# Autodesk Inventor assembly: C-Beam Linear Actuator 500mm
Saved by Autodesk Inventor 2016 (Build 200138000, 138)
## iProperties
Created: 2015-11
Part Number: C-Beam Linear Actuator 500mm
Document SubType Name: Assembly
Designer: John
Author: John
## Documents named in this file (19)
- D:\3D Printer Designs\John Ledden Designs\DLP Printer\V0-4\C-Beam Linear Actuator 500mm.iam
- D:\3D Printer Designs\John Ledden Designs\DLP Printer\V0-4\Low Profile Screw M5_M5 x 20.ipt
- D:\3D Printer Designs\John Ledden Designs\DLP Printer\V0-4\Nylon Insert Lock Nut M5.ipt
- D:\3D Printer Designs\John Ledden Designs\DLP Printer\V0-4\Low Profile Screw M5_M5 x 25.ipt
- D:\3D Printer Designs\John Ledden Designs\DLP Printer\V0-4\Low Profile Screw M5_M5 x 55.ipt
- D:\3D Printer Designs\John Ledden Designs\DLP Printer\V0-4\C-Beam End Mount.ipt
- D:\3D Printer Designs\John Ledden Designs\DLP Printer\V0-4\C-Beam 40x80x500 Linear Rail.ipt
- D:\3D Printer Designs\John Ledden Designs\DLP Printer\V0-4\Ball Bearing 8 x 16 x 5.ipt
- D:\3D Printer Designs\John Ledden Designs\DLP Printer\V0-4\Shim Washer 8mm.ipt
- D:\3D Printer Designs\John Ledden Designs\DLP Printer\V0-4\Lock Collar 8mm.ipt
- D:\3D Printer Designs\John Ledden Designs\DLP Printer\V0-4\Aluminum Spacer 40mm.ipt
- D:\3D Printer Designs\John Ledden Designs\DLP Printer\V0-4\Nema 23 Stepper Motor.ipt
- D:\3D Printer Designs\John Ledden Designs\DLP Printer\V0-4\Flexible Coupling 0.25in x 8mm.ipt
- D:\3D Printer Designs\John Ledden Designs\DLP Printer\V0-4\8mm leadscrew 540mm.ipt
- D:\3D Printer Designs\John Ledden Designs\DLP Printer\V0-4\C-Beam Gantry Plate.ipt
- D:\3D Printer Designs\John Ledden Designs\DLP Printer\V0-4\8mm Acme Nut Block.ipt
- D:\3D Printer Designs\John Ledden Designs\DLP Printer\V0-4\Xtreme Mini V Wheel_Straight.iam
- D:\3D Printer Designs\John Ledden Designs\DLP Printer\V0-4\Xtreme Mini V Wheel_Eccentric.iam
- D:\3D Printer Designs\John Ledden Designs\DLP Printer\V0-4\Aluminum Spacer 3mm.ipt
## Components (40 placed, 40 different names)
1. Low Profile Screw M5_M5 x 20_1102
2. Low Profile Screw M5_M5 x 20_1103
3. Low Profile Screw M5_M5 x 20_1104
4. Low Profile Screw M5_M5 x 20_1105
5. Low Profile Screw M5_M5 x 20_1106
6. Low Profile Screw M5_M5 x 20_1107
7. Low Profile Screw M5_M5 x 20_1108
8. Low Profile Screw M5_M5 x 20_1109
9. Nylon Insert Lock Nut M5_1110
10. Nylon Insert Lock Nut M5_1111
11. Low Profile Screw M5_M5 x 20_1112
12. Low Profile Screw M5_M5 x 20_1113
13. Low Profile Screw M5_M5 x 25_1114
14. Low Profile Screw M5_M5 x 25_1115
15. Low Profile Screw M5_M5 x 25_1116
16. Low Profile Screw M5_M5 x 25_1117
17. Low Profile Screw M5_M5 x 55_1118
18. Low Profile Screw M5_M5 x 55_1119
19. C-Beam End Mount_1120
20. C-Beam 40x80x500 Linear Rail_1121
21. C-Beam End Mount_1122
22. Ball Bearing 8 x 16 x 5_1123
23. Ball Bearing 8 x 16 x 5_1124
24. Shim Washer 8mm_1125
25. Shim Washer 8mm_1126
26. Lock Collar 8mm_1127
27. Lock Collar 8mm_1128
28. Aluminum Spacer 40mm_1129
29. Aluminum Spacer 40mm_1130
30. Nema 23 Stepper Motor_1131
31. Flexible Coupling 0.25in x 8mm_1132
32. 8mm leadscrew 540mm_1133
33. C-Beam Gantry Plate_1134
34. 8mm Acme Nut Block_1135
35. Xtreme Mini V Wheel_Straight_1136 [sub-assembly]
36. Xtreme Mini V Wheel_Straight_1137 [sub-assembly]
37. Xtreme Mini V Wheel_Eccentric_1138 [sub-assembly]
38. Xtreme Mini V Wheel_Eccentric_1139 [sub-assembly]
39. Aluminum Spacer 3mm_1140
40. Aluminum Spacer 3mm_1141
